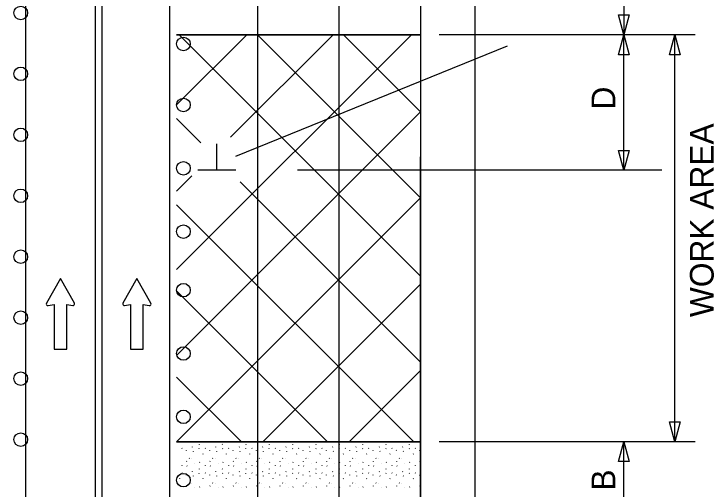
# Model space of a CAD drawing. Extents: x 16723 to 18475, y 7015 to 8267.
# Drawn here: x 17031.7 to 17238.3, y 7769.1 to 7909.4 of the extents above; entities that cross this region are included whole.
import ezdxf

# ---------------------------------------------------------------- set-up
doc = ezdxf.new("R2010")
doc.units = 0
for name, color, linetype in [('ALI_LEGAL_EX', 7, 'Continuous'), ('MT_SCRATCH_LEVEL_A', 7, 'Continuous'), ('MT_SCRATCH_LEVEL_E', 7, 'Continuous'), ('PAVT_EDGE_EX', 7, 'Continuous'), ('TRAFFIC_SIGNS_PR', 7, 'Continuous'), ('TYPICAL_TEXT_DIMEN_PR', 7, 'Continuous')]:
    doc.layers.add(name, color=color, linetype=linetype)

msp = doc.modelspace()

# ---------------------------------------------------------------- linework, layer by layer
at = {"layer": 'ALI_LEGAL_EX'}
for p, q in [((17057.71, 7347.02), (17057.71, 8219.23)), ((17077.71, 7347.02), (17077.71, 8219.23)), ((17103.71, 7341.97), (17103.71, 8214.17)), ((17127.71, 7341.97), (17127.71, 8214.17))]:
    msp.add_line(p, q, dxfattribs=at)
for points in [[(17077.71, 7841.97), (17077.71, 7866.97)], [(17103.71, 7841.97), (17103.71, 7866.97)], [(17127.71, 7841.97), (17127.71, 7866.97)]]:
    msp.add_lwpolyline(points, dxfattribs=at)
at = {"layer": 'MT_SCRATCH_LEVEL_A'}
for p, q in [((17079.71, 7903.21), (17151.71, 7903.21)), ((17151.71, 7903.21), (17079.71, 7903.21)), ((17079.71, 7833.94), (17148.97, 7903.21)), ((17079.71, 7882.49), (17100.43, 7903.21)), ((17151.71, 7831.95), (17080.45, 7903.21)), ((17095.62, 7872.93), (17125.89, 7903.21)), ((17151.71, 7855.03), (17103.54, 7903.21)), ((17151.71, 7880.49), (17128.99, 7903.21)), ((17079.71, 7808.49), (17151.71, 7880.49)), ((17086.89, 7871.31), (17079.71, 7878.49)), ((17151.71, 7867.21), (17151.71, 7754.97)), ((17151.71, 7783.03), (17151.71, 7867.21)), ((17079.71, 7857.03), (17084.19, 7861.51)), ((17151.71, 7806.49), (17098.41, 7859.8)), ((17079.71, 7783.03), (17151.71, 7855.03)), ((17149.72, 7783.03), (17079.71, 7853.04)), ((17105.17, 7783.03), (17151.71, 7829.58)), ((17124.26, 7783.03), (17079.71, 7827.58)), ((17130.62, 7783.03), (17151.71, 7804.12)), ((17098.8, 7783.03), (17079.71, 7802.12)), ((17079.71, 7783.03), (17151.71, 7783.03)), ((17079.71, 7783.03), (17151.71, 7783.03)), ((17151.71, 7783.03), (17079.71, 7783.03)), ((17079.71, 7783.03), (17079.71, 7783.03)), ((17084.38, 7781.42), (17084.43, 7781.54)), ((17086.31, 7782.29), (17086.36, 7782.22)), ((17091.27, 7781.42), (17091.32, 7781.54)), ((17093.19, 7782.29), (17093.24, 7782.22)), ((17098.16, 7781.42), (17098.21, 7781.54)), ((17100.08, 7782.29), (17100.13, 7782.22)), ((17105.04, 7781.42), (17105.1, 7781.54)), ((17106.97, 7782.29), (17107.02, 7782.22)), ((17111.93, 7781.42), (17111.98, 7781.54)), ((17113.86, 7782.29), (17113.91, 7782.22)), ((17118.82, 7781.42), (17118.87, 7781.54)), ((17120.74, 7782.29), (17120.8, 7782.22)), ((17125.71, 7781.42), (17125.76, 7781.54)), ((17127.63, 7782.29), (17127.68, 7782.22)), ((17132.59, 7781.42), (17132.65, 7781.54)), ((17134.52, 7782.29), (17134.57, 7782.22)), ((17139.48, 7781.42), (17139.53, 7781.54)), ((17141.41, 7782.29), (17141.46, 7782.22)), ((17146.37, 7781.42), (17146.42, 7781.54)), ((17148.29, 7782.29), (17148.35, 7782.22)), ((17151.71, 7754.97), (17151.71, 7783.03)), ((17081.26, 7781.14), (17081.31, 7781.07)), ((17082.54, 7780.57), (17082.55, 7780.45)), ((17084.57, 7780.22), (17084.62, 7780.15)), ((17086.35, 7780.89), (17086.4, 7781.01)), ((17087.53, 7779.39), (17087.58, 7779.51)), ((17088.15, 7781.14), (17088.2, 7781.07)), ((17089.43, 7780.57), (17089.44, 7780.45)), ((17091.46, 7780.22), (17091.51, 7780.15)), ((17093.24, 7780.89), (17093.29, 7781.01)), ((17094.41, 7779.39), (17094.47, 7779.51)), ((17095.03, 7781.14), (17095.08, 7781.07)), ((17096.31, 7780.57), (17096.33, 7780.45)), ((17098.34, 7780.22), (17098.4, 7780.15)), ((17100.12, 7780.89), (17100.17, 7781.01)), ((17101.3, 7779.39), (17101.35, 7779.51)), ((17101.92, 7781.14), (17101.97, 7781.07)), ((17103.2, 7780.57), (17103.22, 7780.45)), ((17105.23, 7780.22), (17105.28, 7780.15)), ((17107.01, 7780.89), (17107.06, 7781.01)), ((17108.19, 7779.39), (17108.24, 7779.51)), ((17108.81, 7781.14), (17108.86, 7781.07)), ((17110.09, 7780.57), (17110.1, 7780.45)), ((17112.12, 7780.22), (17112.17, 7780.15)), ((17113.9, 7780.89), (17113.95, 7781.01)), ((17115.08, 7779.39), (17115.13, 7779.51)), ((17115.69, 7781.14), (17115.75, 7781.07)), ((17116.98, 7780.57), (17116.99, 7780.45)), ((17119.01, 7780.22), (17119.06, 7780.15)), ((17120.79, 7780.89), (17120.84, 7781.01)), ((17121.96, 7779.39), (17122.02, 7779.51)), ((17122.58, 7781.14), (17122.63, 7781.07)), ((17123.86, 7780.57), (17123.88, 7780.45)), ((17125.89, 7780.22), (17125.95, 7780.15)), ((17127.67, 7780.89), (17127.73, 7781.01)), ((17128.85, 7779.39), (17128.9, 7779.51)), ((17129.47, 7781.14), (17129.52, 7781.07)), ((17130.75, 7780.57), (17130.76, 7780.45)), ((17132.78, 7780.22), (17132.83, 7780.15)), ((17134.56, 7780.89), (17134.61, 7781.01)), ((17135.74, 7779.39), (17135.79, 7779.51)), ((17136.36, 7781.14), (17136.41, 7781.07)), ((17137.64, 7780.57), (17137.65, 7780.45)), ((17139.67, 7780.22), (17139.72, 7780.15)), ((17141.45, 7780.89), (17141.5, 7781.01)), ((17142.63, 7779.39), (17142.68, 7779.51)), ((17143.24, 7781.14), (17143.3, 7781.07)), ((17144.53, 7780.57), (17144.54, 7780.45)), ((17146.56, 7780.22), (17146.61, 7780.15)), ((17148.34, 7780.89), (17148.39, 7781.01)), ((17149.51, 7779.39), (17149.57, 7779.51)), ((17150.13, 7781.14), (17150.19, 7781.07)), ((17151.42, 7780.57), (17151.43, 7780.45)), ((17082.66, 7777.19), (17082.71, 7777.31)), ((17083.42, 7778.15), (17083.47, 7778.08)), ((17084.16, 7778.12), (17084.21, 7778.05)), ((17089.55, 7777.19), (17089.6, 7777.31)), ((17090.31, 7778.15), (17090.36, 7778.08)), ((17091.05, 7778.12), (17091.1, 7778.05)), ((17096.43, 7777.19), (17096.49, 7777.31)), ((17097.2, 7778.15), (17097.25, 7778.08)), ((17097.94, 7778.12), (17097.99, 7778.05)), ((17103.32, 7777.19), (17103.37, 7777.31)), ((17104.09, 7778.15), (17104.14, 7778.08)), ((17104.82, 7778.12), (17104.88, 7778.05)), ((17110.21, 7777.19), (17110.26, 7777.31)), ((17110.97, 7778.15), (17111.03, 7778.08)), ((17111.71, 7778.12), (17111.76, 7778.05)), ((17117.1, 7777.19), (17117.15, 7777.31)), ((17117.86, 7778.15), (17117.91, 7778.08)), ((17118.6, 7778.12), (17118.65, 7778.05)), ((17123.98, 7777.19), (17124.04, 7777.31)), ((17124.75, 7778.15), (17124.8, 7778.08)), ((17125.49, 7778.12), (17125.54, 7778.05)), ((17130.87, 7777.19), (17130.92, 7777.31)), ((17131.64, 7778.15), (17131.69, 7778.08)), ((17132.37, 7778.12), (17132.42, 7778.05)), ((17137.76, 7777.19), (17137.81, 7777.31)), ((17138.52, 7778.15), (17138.58, 7778.08)), ((17139.26, 7778.12), (17139.31, 7778.05)), ((17144.65, 7777.19), (17144.7, 7777.31)), ((17145.41, 7778.15), (17145.46, 7778.08)), ((17146.15, 7778.12), (17146.2, 7778.05)), ((17151.53, 7777.19), (17151.59, 7777.31)), ((17081.21, 7776.07), (17081.26, 7775.99)), ((17082.74, 7775.93), (17082.79, 7775.85)), ((17085.03, 7776.74), (17085.08, 7776.67)), ((17086.48, 7776.9), (17086.53, 7777.01)), ((17088.1, 7776.07), (17088.15, 7775.99)), ((17089.63, 7775.93), (17089.68, 7775.85)), ((17091.92, 7776.74), (17091.97, 7776.67)), ((17093.37, 7776.9), (17093.42, 7777.01)), ((17094.98, 7776.07), (17095.04, 7775.99)), ((17096.51, 7775.93), (17096.57, 7775.85)), ((17098.8, 7776.74), (17098.86, 7776.67)), ((17100.25, 7776.9), (17100.31, 7777.01)), ((17101.87, 7776.07), (17101.92, 7775.99)), ((17103.4, 7775.93), (17103.45, 7775.85)), ((17105.69, 7776.74), (17105.74, 7776.67)), ((17107.14, 7776.9), (17107.19, 7777.01)), ((17108.76, 7776.07), (17108.81, 7775.99)), ((17110.29, 7775.93), (17110.34, 7775.85)), ((17112.58, 7776.74), (17112.63, 7776.67)), ((17114.03, 7776.9), (17114.08, 7777.01)), ((17115.65, 7776.07), (17115.7, 7775.99)), ((17117.18, 7775.93), (17117.23, 7775.85)), ((17119.47, 7776.74), (17119.52, 7776.67)), ((17120.92, 7776.9), (17120.97, 7777.01)), ((17122.53, 7776.07), (17122.59, 7775.99)), ((17124.06, 7775.93), (17124.12, 7775.85)), ((17126.35, 7776.74), (17126.41, 7776.67)), ((17127.8, 7776.9), (17127.85, 7777.01)), ((17129.42, 7776.07), (17129.47, 7775.99)), ((17130.95, 7775.93), (17131, 7775.85)), ((17133.24, 7776.74), (17133.29, 7776.67)), ((17134.69, 7776.9), (17134.74, 7777.01)), ((17136.31, 7776.07), (17136.36, 7775.99)), ((17137.84, 7775.93), (17137.89, 7775.85)), ((17140.13, 7776.74), (17140.18, 7776.67)), ((17141.58, 7776.9), (17141.63, 7777.01)), ((17143.2, 7776.07), (17143.25, 7775.99)), ((17144.73, 7775.93), (17144.78, 7775.85)), ((17147.02, 7776.74), (17147.07, 7776.67)), ((17148.47, 7776.9), (17148.52, 7777.01)), ((17150.08, 7776.07), (17150.14, 7775.99)), ((17151.61, 7775.93), (17151.67, 7775.85)), ((17081.26, 7773.86), (17081.31, 7773.78)), ((17082.54, 7773.28), (17082.55, 7773.16)), ((17084.38, 7774.14), (17084.43, 7774.25)), ((17086.31, 7775.01), (17086.36, 7774.93)), ((17086.35, 7773.61), (17086.4, 7773.72)), ((17088.15, 7773.86), (17088.2, 7773.78)), ((17089.43, 7773.28), (17089.44, 7773.16)), ((17091.27, 7774.14), (17091.32, 7774.25)), ((17093.19, 7775.01), (17093.24, 7774.93)), ((17093.24, 7773.61), (17093.29, 7773.72)), ((17095.03, 7773.86), (17095.08, 7773.78)), ((17096.31, 7773.28), (17096.33, 7773.16)), ((17098.16, 7774.14), (17098.21, 7774.25)), ((17100.08, 7775.01), (17100.13, 7774.93)), ((17100.12, 7773.61), (17100.17, 7773.72)), ((17101.92, 7773.86), (17101.97, 7773.78)), ((17103.2, 7773.28), (17103.22, 7773.16)), ((17105.04, 7774.14), (17105.1, 7774.25)), ((17106.97, 7775.01), (17107.02, 7774.93)), ((17107.01, 7773.61), (17107.06, 7773.72)), ((17108.81, 7773.86), (17108.86, 7773.78)), ((17110.09, 7773.28), (17110.1, 7773.16)), ((17111.93, 7774.14), (17111.98, 7774.25)), ((17113.86, 7775.01), (17113.91, 7774.93)), ((17113.9, 7773.61), (17113.95, 7773.72)), ((17115.69, 7773.86), (17115.75, 7773.78)), ((17116.98, 7773.28), (17116.99, 7773.16)), ((17118.82, 7774.14), (17118.87, 7774.25)), ((17120.74, 7775.01), (17120.8, 7774.93)), ((17120.79, 7773.61), (17120.84, 7773.72)), ((17122.58, 7773.86), (17122.63, 7773.78)), ((17123.86, 7773.28), (17123.88, 7773.16)), ((17125.71, 7774.14), (17125.76, 7774.25)), ((17127.63, 7775.01), (17127.68, 7774.93)), ((17127.67, 7773.61), (17127.73, 7773.72)), ((17129.47, 7773.86), (17129.52, 7773.78)), ((17130.75, 7773.28), (17130.76, 7773.16)), ((17132.59, 7774.14), (17132.65, 7774.25)), ((17134.52, 7775.01), (17134.57, 7774.93)), ((17134.56, 7773.61), (17134.61, 7773.72)), ((17136.36, 7773.86), (17136.41, 7773.78)), ((17137.64, 7773.28), (17137.65, 7773.16)), ((17139.48, 7774.14), (17139.53, 7774.25)), ((17141.41, 7775.01), (17141.46, 7774.93)), ((17141.45, 7773.61), (17141.5, 7773.72)), ((17143.24, 7773.86), (17143.3, 7773.78)), ((17144.53, 7773.28), (17144.54, 7773.16)), ((17146.37, 7774.14), (17146.42, 7774.25)), ((17148.29, 7775.01), (17148.35, 7774.93)), ((17148.34, 7773.61), (17148.39, 7773.72)), ((17150.13, 7773.86), (17150.19, 7773.78)), ((17151.42, 7773.28), (17151.43, 7773.16)), ((17080.64, 7772.11), (17080.69, 7772.22)), ((17084.57, 7772.94), (17084.62, 7772.86)), ((17087.53, 7772.11), (17087.58, 7772.22)), ((17091.46, 7772.94), (17091.51, 7772.86)), ((17094.41, 7772.11), (17094.47, 7772.22)), ((17098.34, 7772.94), (17098.4, 7772.86)), ((17101.3, 7772.11), (17101.35, 7772.22)), ((17105.23, 7772.94), (17105.28, 7772.86)), ((17108.19, 7772.11), (17108.24, 7772.22)), ((17112.12, 7772.94), (17112.17, 7772.86)), ((17115.08, 7772.11), (17115.13, 7772.22)), ((17119.01, 7772.94), (17119.06, 7772.86)), ((17121.96, 7772.11), (17122.02, 7772.22)), ((17125.89, 7772.94), (17125.95, 7772.86)), ((17128.85, 7772.11), (17128.9, 7772.22)), ((17132.78, 7772.94), (17132.83, 7772.86)), ((17135.74, 7772.11), (17135.79, 7772.22)), ((17139.67, 7772.94), (17139.72, 7772.86)), ((17142.63, 7772.11), (17142.68, 7772.22)), ((17146.56, 7772.94), (17146.61, 7772.86)), ((17149.51, 7772.11), (17149.57, 7772.22)), ((17082.66, 7769.91), (17082.71, 7770.03)), ((17083.42, 7770.87), (17083.47, 7770.79)), ((17084.16, 7770.84), (17084.21, 7770.76)), ((17085.03, 7769.46), (17085.08, 7769.38)), ((17086.48, 7769.61), (17086.53, 7769.73)), ((17089.55, 7769.91), (17089.6, 7770.03)), ((17090.31, 7770.87), (17090.36, 7770.79)), ((17091.05, 7770.84), (17091.1, 7770.76)), ((17091.92, 7769.46), (17091.97, 7769.38)), ((17093.37, 7769.61), (17093.42, 7769.73)), ((17096.43, 7769.91), (17096.49, 7770.03)), ((17097.2, 7770.87), (17097.25, 7770.79)), ((17097.94, 7770.84), (17097.99, 7770.76)), ((17098.8, 7769.46), (17098.86, 7769.38)), ((17100.25, 7769.61), (17100.31, 7769.73)), ((17103.32, 7769.91), (17103.37, 7770.03)), ((17104.09, 7770.87), (17104.14, 7770.79)), ((17104.82, 7770.84), (17104.88, 7770.76)), ((17105.69, 7769.46), (17105.74, 7769.38)), ((17107.14, 7769.61), (17107.19, 7769.73)), ((17110.21, 7769.91), (17110.26, 7770.03)), ((17110.97, 7770.87), (17111.03, 7770.79)), ((17111.71, 7770.84), (17111.76, 7770.76)), ((17112.58, 7769.46), (17112.63, 7769.38)), ((17114.03, 7769.61), (17114.08, 7769.73)), ((17117.1, 7769.91), (17117.15, 7770.03)), ((17117.86, 7770.87), (17117.91, 7770.79)), ((17118.6, 7770.84), (17118.65, 7770.76)), ((17119.47, 7769.46), (17119.52, 7769.38)), ((17120.92, 7769.61), (17120.97, 7769.73)), ((17123.98, 7769.91), (17124.04, 7770.03)), ((17124.75, 7770.87), (17124.8, 7770.79)), ((17125.49, 7770.84), (17125.54, 7770.76)), ((17126.35, 7769.46), (17126.41, 7769.38)), ((17127.8, 7769.61), (17127.85, 7769.73)), ((17130.87, 7769.91), (17130.92, 7770.03)), ((17131.64, 7770.87), (17131.69, 7770.79)), ((17132.37, 7770.84), (17132.42, 7770.76)), ((17133.24, 7769.46), (17133.29, 7769.38)), ((17134.69, 7769.61), (17134.74, 7769.73)), ((17137.76, 7769.91), (17137.81, 7770.03)), ((17138.52, 7770.87), (17138.58, 7770.79)), ((17139.26, 7770.84), (17139.31, 7770.76)), ((17140.13, 7769.46), (17140.18, 7769.38)), ((17141.58, 7769.61), (17141.63, 7769.73)), ((17144.65, 7769.91), (17144.7, 7770.03)), ((17145.41, 7770.87), (17145.46, 7770.79)), ((17146.15, 7770.84), (17146.2, 7770.76)), ((17147.02, 7769.46), (17147.07, 7769.38)), ((17148.47, 7769.61), (17148.52, 7769.73)), ((17151.53, 7769.91), (17151.59, 7770.03))]:
    msp.add_line(p, q, dxfattribs=at)
at = {"layer": 'MT_SCRATCH_LEVEL_E'}
for p, q in [((17045.4, 7831.2), (17041.28, 7823.96)), ((17045.4, 7831.2), (17041.28, 7823.96)), ((17045.4, 7831.2), (17041.28, 7823.96)), ((17045.4, 7831.2), (17041.28, 7823.96)), ((17049.54, 7823.96), (17045.4, 7831.2)), ((17049.54, 7823.96), (17045.4, 7831.2)), ((17049.54, 7823.96), (17045.4, 7831.2)), ((17049.54, 7823.96), (17045.4, 7831.2)), ((17067.97, 7831.2), (17063.86, 7823.96)), ((17067.97, 7831.2), (17063.86, 7823.96)), ((17072.12, 7823.96), (17067.97, 7831.2)), ((17072.12, 7823.96), (17067.97, 7831.2)), ((17041.77, 7823.27), (17043.54, 7823.59)), ((17041.77, 7823.27), (17043.54, 7823.59)), ((17041.77, 7823.27), (17043.54, 7823.59)), ((17041.77, 7823.27), (17043.54, 7823.59)), ((17043.54, 7823.59), (17043.54, 7810.33)), ((17043.54, 7823.59), (17043.54, 7810.33)), ((17043.54, 7823.59), (17043.54, 7810.33)), ((17043.54, 7823.59), (17043.54, 7810.33)), ((17047.28, 7810.33), (17047.28, 7823.59)), ((17047.28, 7823.59), (17049.06, 7823.27)), ((17047.28, 7810.33), (17047.28, 7823.59)), ((17047.28, 7823.59), (17049.06, 7823.27)), ((17047.28, 7810.33), (17047.28, 7823.59)), ((17047.28, 7823.59), (17049.06, 7823.27)), ((17047.28, 7810.33), (17047.28, 7823.59)), ((17047.28, 7823.59), (17049.06, 7823.27)), ((17064.34, 7823.27), (17066.12, 7823.59)), ((17064.34, 7823.27), (17066.12, 7823.59)), ((17066.12, 7823.59), (17066.12, 7810.33)), ((17066.12, 7823.59), (17066.12, 7810.33)), ((17069.86, 7810.33), (17069.86, 7823.59)), ((17069.86, 7823.59), (17071.64, 7823.27)), ((17069.86, 7810.33), (17069.86, 7823.59)), ((17069.86, 7823.59), (17071.64, 7823.27)), ((17043.54, 7810.33), (17047.28, 7810.33)), ((17043.54, 7810.33), (17047.28, 7810.33)), ((17043.54, 7810.33), (17047.28, 7810.33)), ((17043.54, 7810.33), (17047.28, 7810.33)), ((17066.12, 7810.33), (17069.86, 7810.33)), ((17066.12, 7810.33), (17069.86, 7810.33))]:
    msp.add_line(p, q, dxfattribs=at)
for centre, start, end in [((17041.69, 7823.73), 150.4248, 279.9638), ((17041.69, 7823.73), 150.4248, 279.9638), ((17041.69, 7823.73), 150.4248, 279.9638), ((17041.69, 7823.73), 150.4248, 279.9638), ((17049.13, 7823.73), 260.0362, 29.7731), ((17049.13, 7823.73), 260.0362, 29.7731), ((17049.13, 7823.73), 260.0362, 29.7731), ((17049.13, 7823.73), 260.0362, 29.7731), ((17064.27, 7823.73), 150.4248, 279.9638), ((17064.27, 7823.73), 150.4248, 279.9638), ((17071.71, 7823.73), 260.0362, 29.7731), ((17071.71, 7823.73), 260.0362, 29.7731)]:
    msp.add_arc(centre, 0.463, start, end, dxfattribs=at)
at = {"layer": 'PAVT_EDGE_EX'}
for p, q in [((17035.15, 8267.39), (17035.15, 7438.21)), ((17151.71, 8214.17), (17151.71, 7352.81)), ((17167.71, 8214.17), (17167.71, 7352.81)), ((17055.71, 7913.53), (17055.71, 7743.81))]:
    msp.add_line(p, q, dxfattribs=at)
at = {"layer": 'TRAFFIC_SIGNS_PR'}
for centre in [(17033.71, 7909.67), (17081.71, 7900.5), (17033.71, 7891.67), (17081.71, 7882.5), (17033.71, 7873.67), (17081.71, 7863.79), (17033.71, 7855.67), (17081.71, 7845.09), (17033.71, 7837.67), (17081.71, 7827.79), (17033.71, 7819.67), (17081.71, 7809.09), (17033.71, 7801.67), (17081.71, 7790.38), (17033.71, 7783.67), (17081.71, 7771.68)]:
    msp.add_circle(centre, 2, dxfattribs=at)
at = {"layer": 'TYPICAL_TEXT_DIMEN_PR'}
for p, q in [((17211.71, 7927.67), (17211.71, 7903.21)), ((17211.71, 7903.21), (17210.14, 7909.07)), ((17210.14, 7909.07), (17211.71, 7909.07)), ((17211.71, 7909.07), (17213.28, 7909.07)), ((17213.28, 7909.07), (17211.71, 7903.21)), ((17232.76, 7903.21), (17157.22, 7903.21)), ((17210.14, 7897.34), (17211.71, 7903.21)), ((17211.71, 7863.21), (17211.71, 7903.21)), ((17211.71, 7903.21), (17213.28, 7897.34)), ((17225.14, 7897.34), (17226.71, 7903.21)), ((17226.71, 7783.03), (17226.71, 7903.21)), ((17226.71, 7903.21), (17228.28, 7897.34)), ((17177.2, 7899.81), (17097.11, 7867.31)), ((17211.71, 7897.34), (17210.14, 7897.34)), ((17213.28, 7897.34), (17211.71, 7897.34)), ((17226.71, 7897.34), (17225.14, 7897.34)), ((17228.28, 7897.34), (17226.71, 7897.34)), ((17091.55, 7863.2), (17091.55, 7870.98)), ((17211.71, 7863.21), (17210.14, 7869.07)), ((17210.14, 7869.07), (17211.71, 7869.07)), ((17211.71, 7869.07), (17213.28, 7869.07)), ((17213.28, 7869.07), (17211.71, 7863.21)), ((17097.17, 7863.2), (17085.92, 7863.2)), ((17222.84, 7863.21), (17115.42, 7863.21)), ((17226.71, 7783.03), (17225.14, 7788.89)), ((17225.14, 7788.89), (17226.71, 7788.89)), ((17226.71, 7783.03), (17225.14, 7788.89)), ((17225.14, 7788.89), (17226.71, 7788.89)), ((17226.71, 7788.89), (17228.28, 7788.89)), ((17228.28, 7788.89), (17226.71, 7783.03)), ((17226.71, 7788.89), (17228.28, 7788.89)), ((17228.28, 7788.89), (17226.71, 7783.03)), ((17232.76, 7783.03), (17157.22, 7783.03)), ((17210.14, 7777.17), (17211.71, 7783.03)), ((17211.71, 7754.97), (17211.71, 7783.03)), ((17211.71, 7783.03), (17213.28, 7777.17)), ((17211.71, 7777.17), (17210.14, 7777.17)), ((17213.28, 7777.17), (17211.71, 7777.17))]:
    msp.add_line(p, q, dxfattribs=at)

# ---------------------------------------------------------------- texts
for s, p in [('D', (17209.15, 7881.15)), ('WORK AREA', (17238.18, 7819.84)), ('B', (17209.15, 7768.6))]:
    msp.add_text(s, height=7, rotation=90, dxfattribs=at).set_placement(p)

doc.saveas('drawing.dxf')
